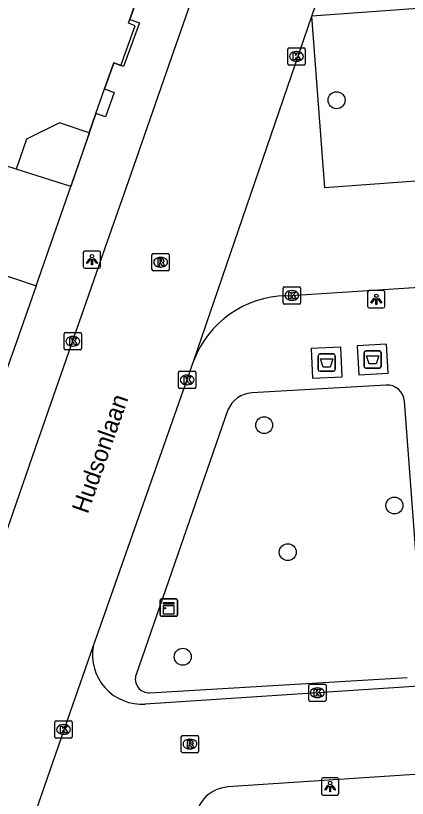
# Model space of a CAD drawing. Extents: x 161253 to 161848, y 384872 to 385383.
# Drawn here: x 161719.89 to 161742.51, y 385099.32 to 385144.57 of the extents above; entities that cross this region are included whole.
import ezdxf

# ---------------------------------------------------------------- set-up
doc = ezdxf.new("R2010")
doc.units = 0
for name, color, linetype in [('IMGEO_Afval_apart_plaats', 7, 'Continuous'), ('IMGEO_Boom', 7, 'Continuous'), ('IMGEO_Hek', 7, 'Continuous'), ('IMGEO_Kast', 7, 'Continuous'), ('IMGEO_Kolk', 7, 'Continuous'), ('IMGEO_Lichtpunt', 7, 'Continuous'), ('IMGEO_Openbare_ruimte_label', 7, 'Continuous'), ('IMGEO_Pand', 7, 'Continuous'), ('IMGEO_Rijbaan_lokaal_open', 7, 'Continuous'), ('IMGEO_Rioolput', 7, 'Continuous'), ('IMGEO_Voetpad_gesloten', 7, 'Continuous'), ('IMGEO_Voetpad_open', 7, 'Continuous')]:
    doc.layers.add(name, color=color, linetype=linetype)

msp = doc.modelspace()

# ---------------------------------------------------------------- linework, layer by layer
at = {"layer": 'IMGEO_Afval_apart_plaats'}
for p, q in [((161740.005, 385124.292), (161740.005, 385125.092)), ((161740.005, 385125.092), (161740.005, 385124.292)), ((161740.105, 385125.192), (161740.895, 385125.192)), ((161740.895, 385125.192), (161740.105, 385125.192)), ((161740.995, 385125.092), (161740.995, 385124.292)), ((161740.995, 385124.292), (161740.995, 385125.092)), ((161737.357, 385124.112), (161737.357, 385124.912)), ((161737.357, 385124.912), (161737.357, 385124.112)), ((161737.457, 385125.012), (161738.247, 385125.012)), ((161738.247, 385125.012), (161737.457, 385125.012)), ((161738.347, 385124.912), (161738.347, 385124.112)), ((161738.347, 385124.112), (161738.347, 385124.912)), ((161740.895, 385124.192), (161740.105, 385124.192)), ((161740.105, 385124.192), (161740.895, 385124.192)), ((161738.247, 385124.012), (161737.457, 385124.012)), ((161737.457, 385124.012), (161738.247, 385124.012))]:
    msp.add_line(p, q, dxfattribs=at)
for points in [[(161737.5, 385124.726), (161738.204, 385124.726), (161738.055, 385124.256), (161737.649, 385124.256), (161737.5, 385124.726)], [(161740.148, 385124.906), (161740.852, 385124.906), (161740.703, 385124.436), (161740.297, 385124.436), (161740.148, 385124.906)]]:
    msp.add_lwpolyline(points, dxfattribs=at)
for centre, start, end in [((161740.105, 385125.092), 90, 180), ((161740.105, 385125.092), 90, 180), ((161740.895, 385125.092), 0, 90), ((161740.895, 385125.092), 360, 90), ((161737.457, 385124.912), 90, 180), ((161737.457, 385124.912), 90, 180), ((161738.247, 385124.912), 0, 90), ((161738.247, 385124.912), 360, 90), ((161740.105, 385124.292), 180, 270), ((161740.105, 385124.292), 180, 270), ((161740.895, 385124.292), 270, 0), ((161740.895, 385124.292), 270, 0), ((161737.457, 385124.112), 180, 270), ((161737.457, 385124.112), 180, 270), ((161738.247, 385124.112), 270, 0), ((161738.247, 385124.112), 270, 0)]:
    msp.add_arc(centre, 0.1, start, end, dxfattribs=at)
at = {"layer": 'IMGEO_Boom'}
for centre in [(161738.423, 385139.682), (161734.242, 385120.895), (161741.76, 385116.25), (161735.602, 385113.549), (161729.538, 385107.505)]:
    msp.add_circle(centre, 0.489, dxfattribs=at)
at = {"layer": 'IMGEO_Hek'}
msp.add_lwpolyline([(161737.265, 385175.182), (161735.876, 385171.238), (161736.442, 385171.041), (161735.549, 385168.482), (161734.983, 385168.68), (161732.722, 385162.2), (161733.288, 385162), (161731.516, 385156.988), (161730.95, 385157.188), (161728.038, 385148.925), (161728.606, 385148.733), (161728.145, 385147.368), (161727.577, 385147.56), (161726.478, 385144.356), (161727.042, 385144.151), (161726.125, 385141.631), (161725.562, 385141.836), (161725.015, 385140.334), (161725.581, 385140.136), (161725.087, 385138.721), (161724.52, 385138.919), (161723.087, 385134.7)], dxfattribs=at)
at = {"layer": 'IMGEO_Kast'}
for p, q in [((161728.235, 385109.92), (161728.235, 385110.761)), ((161728.235, 385110.761), (161728.235, 385109.92)), ((161728.31, 385110.845), (161729.151, 385110.845)), ((161729.151, 385110.845), (161728.31, 385110.845)), ((161729.235, 385110.77), (161729.235, 385109.929)), ((161729.235, 385109.929), (161729.235, 385110.77)), ((161729.16, 385109.845), (161728.319, 385109.845)), ((161728.319, 385109.845), (161729.16, 385109.845))]:
    msp.add_line(p, q, dxfattribs=at)
for points in [[(161728.43, 385110.635), (161729.03, 385110.635), (161729.03, 385110.55), (161728.43, 385110.55), (161728.43, 385110.635)], [(161728.43, 385110.46), (161729.03, 385110.46), (161729.03, 385109.971), (161728.43, 385109.971), (161728.43, 385110.46)]]:
    msp.add_lwpolyline(points, dxfattribs=at)
msp.add_circle((161728.514, 385110.309), 0.0377, dxfattribs=at)
for centre, start, end in [((161728.313, 385110.767), 92.4484, 184.2845), ((161728.313, 385110.767), 92.4484, 184.2845), ((161729.157, 385110.767), 2.4484, 94.2845), ((161729.157, 385110.767), 2.4484, 94.2845), ((161728.313, 385109.923), 182.4484, 274.2845), ((161728.313, 385109.923), 182.4484, 274.2845), ((161729.157, 385109.923), 272.4484, 4.2845), ((161729.157, 385109.923), 272.4484, 4.2845)]:
    msp.add_arc(centre, 0.0779, start, end, dxfattribs=at)
at = {"layer": 'IMGEO_Kolk'}
for p, q in [((161735.677, 385142.715), (161736.529, 385142.715)), ((161735.602, 385141.789), (161735.602, 385142.641)), ((161736.09, 385142.495), (161736.115, 385142.495)), ((161736.603, 385142.641), (161736.603, 385141.789)), ((161736.113, 385141.935), (161736.088, 385141.935)), ((161736.529, 385141.715), (161735.677, 385141.715)), ((161735.337, 385127.967), (161735.337, 385128.819)), ((161735.412, 385128.893), (161736.264, 385128.893)), ((161735.825, 385128.673), (161735.85, 385128.673)), ((161736.338, 385128.819), (161736.338, 385127.967)), ((161736.264, 385127.893), (161735.412, 385127.893)), ((161735.848, 385128.113), (161735.823, 385128.113)), ((161722.699, 385125.318), (161722.699, 385126.17)), ((161722.774, 385126.244), (161723.626, 385126.244)), ((161723.187, 385126.024), (161723.212, 385126.024)), ((161723.7, 385126.17), (161723.7, 385125.318)), ((161723.626, 385125.244), (161722.774, 385125.244)), ((161723.21, 385125.464), (161723.185, 385125.464)), ((161729.296, 385123.087), (161729.296, 385123.939)), ((161729.371, 385124.013), (161730.223, 385124.013)), ((161729.784, 385123.793), (161729.809, 385123.793)), ((161730.297, 385123.939), (161730.297, 385123.087)), ((161729.807, 385123.233), (161729.782, 385123.233)), ((161730.223, 385123.013), (161729.371, 385123.013)), ((161736.811, 385104.999), (161736.811, 385105.851)), ((161736.886, 385105.925), (161737.738, 385105.925)), ((161737.299, 385105.705), (161737.324, 385105.705)), ((161737.812, 385105.851), (161737.812, 385104.999)), ((161737.322, 385105.145), (161737.297, 385105.145)), ((161737.738, 385104.925), (161736.886, 385104.925)), ((161722.228, 385103.799), (161723.08, 385103.799)), ((161722.153, 385102.873), (161722.153, 385103.725)), ((161722.641, 385103.579), (161722.666, 385103.579)), ((161723.154, 385103.725), (161723.154, 385102.873)), ((161722.664, 385103.019), (161722.639, 385103.019)), ((161723.08, 385102.799), (161722.228, 385102.799))]:
    msp.add_line(p, q, dxfattribs=at)
for points in [[(161735.677, 385142.715), (161736.529, 385142.715)], [(161735.602, 385141.789), (161735.602, 385142.641)], [(161735.923, 385142.415), (161736.046, 385142.415), (161736.046, 385142.264), (161736.176, 385142.415), (161736.34, 385142.415), (161736.194, 385142.264), (161736.347, 385142.015), (161736.195, 385142.015), (161736.11, 385142.179), (161736.046, 385142.112), (161736.046, 385142.015), (161735.923, 385142.015), (161735.923, 385142.415)], [(161736.603, 385142.641), (161736.603, 385141.789)], [(161736.529, 385141.715), (161735.677, 385141.715)], [(161735.337, 385127.967), (161735.337, 385128.819)], [(161735.412, 385128.893), (161736.264, 385128.893)], [(161736.338, 385128.819), (161736.338, 385127.967)], [(161735.658, 385128.593), (161735.781, 385128.593), (161735.781, 385128.442), (161735.911, 385128.593), (161736.075, 385128.593), (161735.929, 385128.442), (161736.082, 385128.193), (161735.93, 385128.193), (161735.845, 385128.357), (161735.781, 385128.29), (161735.781, 385128.193), (161735.658, 385128.193), (161735.658, 385128.593)], [(161736.264, 385127.893), (161735.412, 385127.893)], [(161722.699, 385125.318), (161722.699, 385126.17)], [(161722.774, 385126.244), (161723.626, 385126.244)], [(161723.7, 385126.17), (161723.7, 385125.318)], [(161723.02, 385125.944), (161723.143, 385125.944), (161723.143, 385125.793), (161723.273, 385125.944), (161723.437, 385125.944), (161723.291, 385125.793), (161723.444, 385125.544), (161723.292, 385125.544), (161723.207, 385125.708), (161723.143, 385125.641), (161723.143, 385125.544), (161723.02, 385125.544), (161723.02, 385125.944)], [(161723.626, 385125.244), (161722.774, 385125.244)], [(161729.296, 385123.087), (161729.296, 385123.939)], [(161729.371, 385124.013), (161730.223, 385124.013)], [(161729.617, 385123.713), (161729.74, 385123.713), (161729.74, 385123.562), (161729.87, 385123.713), (161730.034, 385123.713), (161729.888, 385123.562), (161730.041, 385123.313), (161729.889, 385123.313), (161729.804, 385123.477), (161729.74, 385123.41), (161729.74, 385123.313), (161729.617, 385123.313), (161729.617, 385123.713)], [(161730.297, 385123.939), (161730.297, 385123.087)], [(161730.223, 385123.013), (161729.371, 385123.013)], [(161736.811, 385104.999), (161736.811, 385105.851)], [(161736.886, 385105.925), (161737.738, 385105.925)], [(161737.132, 385105.625), (161737.255, 385105.625), (161737.255, 385105.474), (161737.385, 385105.625), (161737.549, 385105.625), (161737.403, 385105.474), (161737.556, 385105.225), (161737.404, 385105.225), (161737.319, 385105.389), (161737.255, 385105.322), (161737.255, 385105.225), (161737.132, 385105.225), (161737.132, 385105.625)], [(161737.812, 385105.851), (161737.812, 385104.999)], [(161737.738, 385104.925), (161736.886, 385104.925)], [(161722.228, 385103.799), (161723.08, 385103.799)], [(161722.153, 385102.873), (161722.153, 385103.725)], [(161722.474, 385103.499), (161722.597, 385103.499), (161722.597, 385103.348), (161722.727, 385103.499), (161722.891, 385103.499), (161722.745, 385103.348), (161722.898, 385103.099), (161722.746, 385103.099), (161722.661, 385103.263), (161722.597, 385103.196), (161722.597, 385103.099), (161722.474, 385103.099), (161722.474, 385103.499)], [(161723.154, 385103.725), (161723.154, 385102.873)], [(161723.08, 385102.799), (161722.228, 385102.799)]]:
    msp.add_lwpolyline(points, dxfattribs=at)
for centre, start, end in [((161735.679, 385142.639), 91.552, 178.448), ((161735.679, 385142.639), 91.552, 178.448), ((161736.527, 385142.639), 1.552, 88.448), ((161736.527, 385142.639), 1.552, 88.448), ((161735.679, 385141.791), 181.552, 268.448), ((161735.679, 385141.791), 181.552, 268.448), ((161736.527, 385141.791), 271.552, 358.448), ((161736.527, 385141.791), 271.552, 358.448), ((161735.414, 385128.817), 91.552, 178.448), ((161735.414, 385128.817), 91.552, 178.448), ((161736.262, 385128.817), 1.552, 88.448), ((161736.262, 385128.817), 1.552, 88.448), ((161735.414, 385127.969), 181.552, 268.448), ((161735.414, 385127.969), 181.552, 268.448), ((161736.262, 385127.969), 271.552, 358.448), ((161736.262, 385127.969), 271.552, 358.448), ((161722.776, 385126.168), 91.552, 178.448), ((161722.776, 385126.168), 91.552, 178.448), ((161723.624, 385126.168), 1.552, 88.448), ((161723.624, 385126.168), 1.552, 88.448), ((161722.776, 385125.32), 181.552, 268.448), ((161722.776, 385125.32), 181.552, 268.448), ((161723.624, 385125.32), 271.552, 358.448), ((161723.624, 385125.32), 271.552, 358.448), ((161729.373, 385123.937), 91.552, 178.448), ((161729.373, 385123.937), 91.552, 178.448), ((161730.221, 385123.937), 1.552, 88.448), ((161730.221, 385123.937), 1.552, 88.448), ((161729.373, 385123.089), 181.552, 268.448), ((161729.373, 385123.089), 181.552, 268.448), ((161730.221, 385123.089), 271.552, 358.448), ((161730.221, 385123.089), 271.552, 358.448), ((161736.888, 385105.849), 91.552, 178.448), ((161736.888, 385105.849), 91.552, 178.448), ((161737.736, 385105.849), 1.552, 88.448), ((161737.736, 385105.849), 1.552, 88.448), ((161736.888, 385105.001), 181.552, 268.448), ((161736.888, 385105.001), 181.552, 268.448), ((161737.736, 385105.001), 271.552, 358.448), ((161737.736, 385105.001), 271.552, 358.448), ((161722.23, 385103.723), 91.552, 178.448), ((161722.23, 385103.723), 91.552, 178.448), ((161723.078, 385103.723), 1.552, 88.448), ((161723.078, 385103.723), 1.552, 88.448), ((161722.23, 385102.875), 181.552, 268.448), ((161722.23, 385102.875), 181.552, 268.448), ((161723.078, 385102.875), 271.552, 358.448), ((161723.078, 385102.875), 271.552, 358.448)]:
    msp.add_arc(centre, 0.0765, start, end, dxfattribs=at)
for centre, major_axis, ratio, start_param, end_param in [((161736.089, 385142.215), (-0.387, 0.002), 0.722429, 4.712389, 7.853982), ((161736.114, 385142.215), (-0.39, 0.002), 0.717154, 1.570796, 4.712389), ((161735.824, 385128.393), (-0.387, 0.002), 0.722429, 4.712389, 7.853982), ((161735.849, 385128.393), (-0.39, 0.002), 0.717154, 1.570796, 4.712389), ((161723.186, 385125.744), (-0.387, 0.002), 0.722429, 4.712389, 7.853982), ((161723.211, 385125.744), (-0.39, 0.002), 0.717154, 1.570796, 4.712389), ((161729.783, 385123.513), (-0.387, 0.002), 0.722429, 4.712389, 7.853982), ((161729.808, 385123.513), (-0.39, 0.002), 0.717154, 1.570796, 4.712389), ((161737.298, 385105.425), (-0.387, 0.002), 0.722429, 4.712389, 7.853982), ((161737.323, 385105.425), (-0.39, 0.002), 0.717154, 1.570796, 4.712389), ((161722.64, 385103.299), (-0.387, 0.002), 0.722429, 4.712389, 7.853982), ((161722.665, 385103.299), (-0.39, 0.002), 0.717154, 1.570796, 4.712389)]:
    msp.add_ellipse(centre, major_axis=major_axis, ratio=ratio, start_param=start_param, end_param=end_param, dxfattribs=at)
at = {"layer": 'IMGEO_Lichtpunt'}
for p, q in [((161724.702, 385130.964), (161723.894, 385130.964)), ((161724.702, 385130.964), (161723.894, 385130.964)), ((161723.8, 385130.869), (161723.8, 385130.062)), ((161723.8, 385130.869), (161723.8, 385130.062)), ((161724.796, 385130.062), (161724.796, 385130.869)), ((161724.796, 385130.062), (161724.796, 385130.869)), ((161723.894, 385129.968), (161724.702, 385129.968)), ((161723.894, 385129.968), (161724.702, 385129.968)), ((161741.118, 385128.674), (161740.31, 385128.674)), ((161741.118, 385128.674), (161740.31, 385128.674)), ((161740.216, 385128.579), (161740.216, 385127.772)), ((161740.216, 385128.579), (161740.216, 385127.772)), ((161741.212, 385127.772), (161741.212, 385128.579)), ((161741.212, 385127.772), (161741.212, 385128.579)), ((161740.31, 385127.678), (161741.118, 385127.678)), ((161740.31, 385127.678), (161741.118, 385127.678)), ((161737.55, 385100.407), (161737.55, 385099.6)), ((161737.55, 385100.407), (161737.55, 385099.6)), ((161738.452, 385100.502), (161737.644, 385100.502)), ((161738.452, 385100.502), (161737.644, 385100.502)), ((161738.546, 385099.6), (161738.546, 385100.407)), ((161738.546, 385099.6), (161738.546, 385100.407)), ((161737.644, 385099.506), (161738.452, 385099.506)), ((161737.644, 385099.506), (161738.452, 385099.506))]:
    msp.add_line(p, q, dxfattribs=at)
for points in [[(161724.174, 385130.533), (161724.213, 385130.505), (161724.025, 385130.243), (161723.987, 385130.27), (161724.174, 385130.533)], [(161724.276, 385130.485), (161724.323, 385130.485), (161724.323, 385130.163), (161724.276, 385130.163), (161724.276, 385130.485)], [(161724.386, 385130.505), (161724.424, 385130.532), (161724.611, 385130.27), (161724.572, 385130.242), (161724.386, 385130.505)], [(161740.59, 385128.243), (161740.629, 385128.215), (161740.441, 385127.953), (161740.403, 385127.98), (161740.59, 385128.243)], [(161740.802, 385128.215), (161740.84, 385128.242), (161741.027, 385127.98), (161740.988, 385127.952), (161740.802, 385128.215)], [(161740.692, 385128.195), (161740.739, 385128.195), (161740.739, 385127.873), (161740.692, 385127.873), (161740.692, 385128.195)], [(161737.924, 385100.071), (161737.963, 385100.043), (161737.775, 385099.781), (161737.737, 385099.808), (161737.924, 385100.071)], [(161738.026, 385100.023), (161738.073, 385100.023), (161738.073, 385099.701), (161738.026, 385099.701), (161738.026, 385100.023)], [(161738.136, 385100.043), (161738.174, 385100.07), (161738.361, 385099.808), (161738.322, 385099.78), (161738.136, 385100.043)]]:
    msp.add_lwpolyline(points, dxfattribs=at)
for centre in [(161724.299, 385130.667), (161740.715, 385128.377), (161738.049, 385100.205)]:
    msp.add_circle(centre, 0.0994, dxfattribs=at)
for centre, start, end in [((161723.894, 385130.869), 90, 180), ((161723.894, 385130.869), 90, 180), ((161724.702, 385130.869), 0, 90), ((161724.702, 385130.869), 0, 90), ((161723.894, 385130.062), 180, 270), ((161723.894, 385130.062), 180, 270), ((161724.702, 385130.062), 270, 0), ((161724.702, 385130.062), 270, 360), ((161740.31, 385128.579), 90, 180), ((161740.31, 385128.579), 90, 180), ((161741.118, 385128.579), 0, 90), ((161741.118, 385128.579), 0, 90), ((161740.31, 385127.772), 180, 270), ((161740.31, 385127.772), 180, 270), ((161741.118, 385127.772), 270, 0), ((161741.118, 385127.772), 270, 360), ((161737.644, 385100.407), 90, 180), ((161737.644, 385100.407), 90, 180), ((161738.452, 385100.407), 0, 90), ((161738.452, 385100.407), 0, 90), ((161737.644, 385099.6), 180, 270), ((161737.644, 385099.6), 180, 270), ((161738.452, 385099.6), 270, 0), ((161738.452, 385099.6), 270, 360)]:
    msp.add_arc(centre, 0.0946, start, end, dxfattribs=at)
at = {"layer": 'IMGEO_Pand'}
for points in [[(161724.136, 385137.789), (161722.418, 385138.37), (161720.515, 385137.433), (161719.931, 385135.706)], [(161723.087, 385134.7), (161724.161, 385137.781), (161724.136, 385137.789)], [(161719.931, 385135.706), (161717.172, 385136.586), (161715.209, 385130.942)], [(161723.087, 385134.7), (161719.931, 385135.706)], [(161721.074, 385128.958), (161723.087, 385134.7)], [(161715.209, 385130.942), (161721.074, 385128.958)], [(161721.074, 385128.958), (161719.684, 385124.995), (161719.31, 385123.928)]]:
    msp.add_lwpolyline(points, dxfattribs=at)
at = {"layer": 'IMGEO_Rijbaan_lokaal_open'}
for points in [[(161748.691, 385199.073), (161746.496, 385192.764), (161744.729, 385187.689), (161743.496, 385184.145), (161742.239, 385180.533), (161740.353, 385175.113), (161739.265, 385171.989), (161738.082, 385168.59), (161735.971, 385162.524), (161733.929, 385156.655), (161729.825, 385144.865), (161728.735, 385141.731), (161726.38, 385134.965), (161725.176, 385131.507), (161724.256, 385128.864), (161723.257, 385125.992), (161722.216, 385123.001), (161721.019, 385119.561), (161719.722, 385115.834), (161718.569, 385112.522), (161715.504, 385103.716)], [(161736.996, 385144.544), (161740.956, 385156.108), (161742.83, 385161.454)], [(161760.378, 385146.252), (161736.996, 385144.544)], [(161730.177, 385124.632), (161736.996, 385144.544)], [(161761.09, 385136.334), (161737.736, 385134.622), (161736.996, 385144.544)], [(161735.494, 385128.372), (161754.736, 385129.631), (161766.603, 385130.405)], [(161724.372, 385108.099), (161724.577, 385108.69), (161724.675, 385108.97), (161730.177, 385124.632)], [(161713.621, 385067.908), (161718.737, 385091.888), (161723.047, 385104.286), (161724.372, 385108.099)], [(161744.939, 385105.909), (161727.375, 385104.765)], [(161745.272, 385100.841), (161732.142, 385099.973)]]:
    msp.add_lwpolyline(points, dxfattribs=at)
for centre, radius, start, end in [((161735.598, 385122.574), 5.799, 91.0312, 159.2142), ((161727.183, 385107.611), 2.853, 170.1526, 273.8674), ((161732.275, 385097.97), 2.007, 93.8092, 183.8987)]:
    msp.add_arc(centre, radius, start, end, dxfattribs=at)
at = {"layer": 'IMGEO_Rioolput'}
for p, q in [((161727.762, 385129.89), (161727.762, 385130.742)), ((161727.837, 385130.816), (161728.689, 385130.816)), ((161728.25, 385130.596), (161728.275, 385130.596)), ((161728.763, 385130.742), (161728.763, 385129.89)), ((161728.273, 385130.036), (161728.248, 385130.036)), ((161728.689, 385129.816), (161727.837, 385129.816)), ((161729.455, 385102.03), (161729.455, 385102.882)), ((161729.53, 385102.956), (161730.382, 385102.956)), ((161730.456, 385102.882), (161730.456, 385102.03)), ((161729.943, 385102.736), (161729.968, 385102.736)), ((161729.966, 385102.176), (161729.941, 385102.176)), ((161730.382, 385101.956), (161729.53, 385101.956))]:
    msp.add_line(p, q, dxfattribs=at)
for points in [[(161727.762, 385129.89), (161727.762, 385130.742)], [(161727.837, 385130.816), (161728.689, 385130.816)], [(161728.351, 385130.514), (161728.099, 385130.516), (161728.099, 385130.116)], [(161728.763, 385130.742), (161728.763, 385129.89)], [(161728.099, 385130.116), (161728.223, 385130.116), (161728.223, 385130.278), (161728.234, 385130.278)], [(161728.277, 385130.435), (161728.223, 385130.435), (161728.223, 385130.354)], [(161728.223, 385130.354), (161728.275, 385130.354)], [(161728.281, 385130.249), (161728.352, 385130.116), (161728.492, 385130.116), (161728.427, 385130.242)], [(161728.689, 385129.816), (161727.837, 385129.816)], [(161729.455, 385102.03), (161729.455, 385102.882)], [(161729.53, 385102.956), (161730.382, 385102.956)], [(161730.456, 385102.882), (161730.456, 385102.03)], [(161730.044, 385102.654), (161729.792, 385102.656), (161729.792, 385102.256)], [(161729.792, 385102.256), (161729.916, 385102.256), (161729.916, 385102.418), (161729.927, 385102.418)], [(161729.97, 385102.575), (161729.916, 385102.575), (161729.916, 385102.494)], [(161729.916, 385102.494), (161729.968, 385102.494)], [(161729.974, 385102.389), (161730.045, 385102.256), (161730.185, 385102.256), (161730.12, 385102.382)], [(161730.382, 385101.956), (161729.53, 385101.956)]]:
    msp.add_lwpolyline(points, dxfattribs=at)
for centre, radius, start, end in [((161727.839, 385130.74), 0.0765, 91.552, 178.448), ((161727.839, 385130.74), 0.0765, 91.552, 178.448), ((161728.35, 385130.404), 0.109, 350.3612, 89.416), ((161728.687, 385130.74), 0.0765, 1.552, 88.448), ((161728.687, 385130.74), 0.0765, 1.552, 88.448), ((161728.233, 385130.225), 0.0533, 26.0293, 88.6989), ((161728.259, 385130.543), 0.19, 274.7715, 282.9687), ((161728.283, 385130.339), 0.0964, 77.0061, 93.1865), ((161728.297, 385130.396), 0.0378, 276.6634, 79.6772), ((161728.348, 385130.404), 0.112, 277.5842, 350.9817), ((161728.332, 385130.189), 0.108, 29.5134, 73.7905), ((161727.839, 385129.892), 0.0765, 181.552, 268.448), ((161727.839, 385129.892), 0.0765, 181.552, 268.448), ((161728.687, 385129.892), 0.0765, 271.552, 358.448), ((161728.687, 385129.892), 0.0765, 271.552, 358.448), ((161729.532, 385102.88), 0.0765, 91.552, 178.448), ((161729.532, 385102.88), 0.0765, 91.552, 178.448), ((161730.38, 385102.88), 0.0765, 1.552, 88.448), ((161730.38, 385102.88), 0.0765, 1.552, 88.448), ((161729.926, 385102.365), 0.0533, 26.0293, 88.6989), ((161729.952, 385102.683), 0.19, 274.7715, 282.9687), ((161729.976, 385102.479), 0.0964, 77.0061, 93.1865), ((161729.99, 385102.536), 0.0378, 276.6634, 79.6772), ((161730.043, 385102.544), 0.109, 350.3612, 89.416), ((161730.041, 385102.544), 0.112, 277.5842, 350.9817), ((161730.025, 385102.329), 0.108, 29.5134, 73.7905), ((161729.532, 385102.032), 0.0765, 181.552, 268.448), ((161729.532, 385102.032), 0.0765, 181.552, 268.448), ((161730.38, 385102.032), 0.0765, 271.552, 358.448), ((161730.38, 385102.032), 0.0765, 271.552, 358.448)]:
    msp.add_arc(centre, radius, start, end, dxfattribs=at)
for centre, major_axis, ratio, start_param, end_param in [((161728.249, 385130.316), (-0.387, 0.002), 0.722429, 4.712389, 7.853982), ((161728.274, 385130.316), (-0.39, 0.002), 0.717154, 1.570796, 4.712389), ((161729.942, 385102.456), (-0.387, 0.002), 0.722429, 4.712389, 7.853982), ((161729.967, 385102.456), (-0.39, 0.002), 0.717154, 1.570796, 4.712389)]:
    msp.add_ellipse(centre, major_axis=major_axis, ratio=ratio, start_param=start_param, end_param=end_param, dxfattribs=at)
at = {"layer": 'IMGEO_Voetpad_gesloten'}
for points in [[(161741.301, 385125.584), (161739.604, 385125.489), (161739.699, 385123.8), (161741.396, 385123.895), (161741.301, 385125.584)], [(161738.67, 385125.408), (161736.955, 385125.328), (161737.035, 385123.616), (161738.75, 385123.696), (161738.67, 385125.408)]]:
    msp.add_lwpolyline(points, dxfattribs=at)
at = {"layer": 'IMGEO_Voetpad_open'}
for points in [[(161724.136, 385137.789), (161724.52, 385138.919), (161725.015, 385140.334), (161725.562, 385141.836), (161725.965, 385141.689), (161726.801, 385143.986), (161726.406, 385144.146), (161727.577, 385147.56), (161728.145, 385147.368), (161728.606, 385148.733), (161728.038, 385148.925), (161730.95, 385157.188), (161731.516, 385156.988), (161733.288, 385162), (161732.722, 385162.2), (161734.983, 385168.68), (161735.549, 385168.482), (161736.442, 385171.041), (161735.876, 385171.238), (161737.265, 385175.182)], [(161741.276, 385123.214), (161733.529, 385122.765)], [(161743.453, 385107.377), (161742.337, 385122.285)], [(161732.152, 385121.776), (161726.847, 385106.475)], [(161727.646, 385105.417), (161742.506, 385106.294)]]:
    msp.add_lwpolyline(points, dxfattribs=at)
for centre, radius, start, end in [((161741.332, 385122.208), 1.008, 4.3996, 93.1903), ((161733.641, 385121.156), 1.613, 93.9768, 157.3971), ((161727.598, 385106.212), 0.796, 160.6928, 273.4273)]:
    msp.add_arc(centre, radius, start, end, dxfattribs=at)

# ---------------------------------------------------------------- texts
at = {"layer": 'IMGEO_Openbare_ruimte_label'}
msp.add_text('Hudsonlaan', height=1, rotation=70.6775, dxfattribs=at).set_placement((161724.053, 385115.722))

doc.saveas('drawing.dxf')
